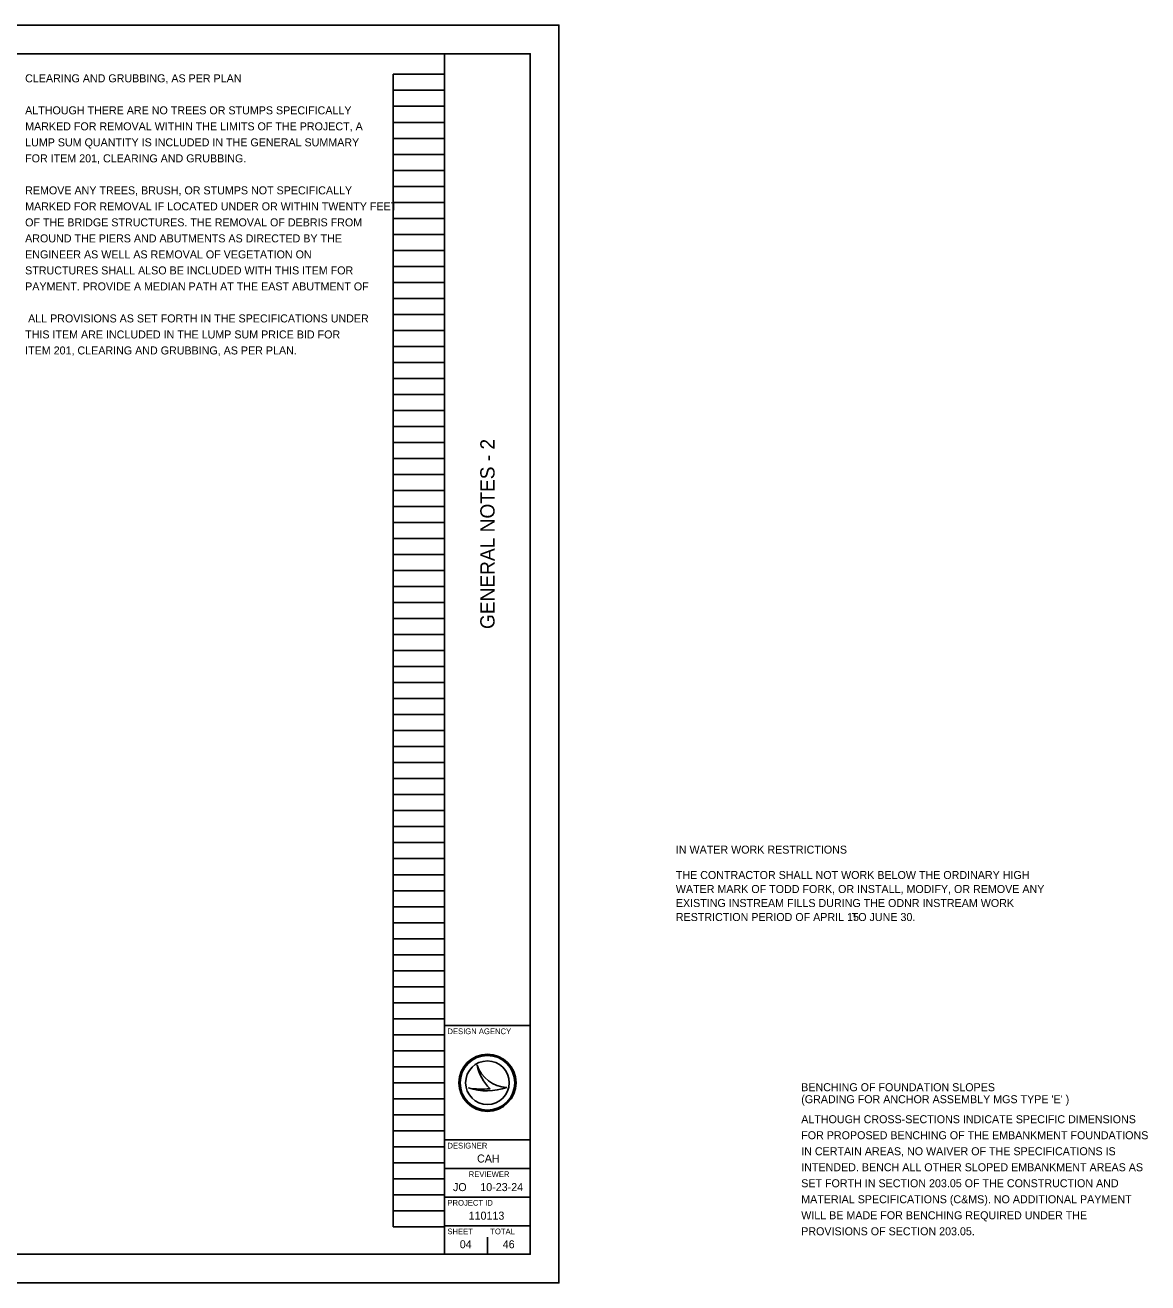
# Model space of a CAD drawing. Extents: x -10.1 to 44.3, y -20.7 to 25.5.
# Drawn here: x 24.66 to 44.31, y 0 to 22 of the extents above; entities that cross this region are included whole.
import ezdxf

# ---------------------------------------------------------------- set-up
doc = ezdxf.new("R2010")
doc.units = 0
for name, color, linetype in [('SH_Border', 7, 'Continuous'), ('SH_Cut_Line', 7, 'Continuous'), ('SH_Data', 7, 'Continuous'), ('SH_Text', 7, 'Continuous')]:
    doc.layers.add(name, color=color, linetype=linetype)

msp = doc.modelspace()

# ---------------------------------------------------------------- linework, layer by layer
at = {"layer": 'SH_Border'}
for p, q in [((32, 0.5), (32, 21.5)), ((32, 4.5), (33.5, 4.5)), ((32, 2.5), (33.5, 2.5)), ((32, 2), (33.5, 2)), ((32, 1.5), (33.5, 1.5)), ((32, 1), (33.5, 1))]:
    msp.add_line(p, q, dxfattribs=at)
msp.add_lwpolyline([(1.5, 21.5), (33.5, 21.5), (33.5, 0.5), (1.5, 0.5)], close=True, dxfattribs=at)
at = {"layer": 'SH_Cut_Line'}
msp.add_lwpolyline([(0, 0), (34, 0), (34, 22), (0, 22)], close=True, dxfattribs=at)
at = {"layer": 'SH_Data'}
for p, q in [((31.1, 0.98), (31.1, 21.14)), ((31.1, 21.14), (32, 21.14)), ((32, 0.98), (32, 21.14)), ((31.1, 20.86), (32, 20.86)), ((31.1, 20.58), (32, 20.58)), ((31.1, 20.3), (32, 20.3)), ((31.1, 20.02), (32, 20.02)), ((31.1, 19.74), (32, 19.74)), ((31.1, 19.46), (32, 19.46)), ((31.1, 19.18), (32, 19.18)), ((31.1, 18.9), (32, 18.9)), ((31.1, 18.62), (32, 18.62)), ((31.1, 18.34), (32, 18.34)), ((31.1, 18.06), (32, 18.06)), ((31.1, 17.78), (32, 17.78)), ((31.1, 17.5), (32, 17.5)), ((31.1, 17.22), (32, 17.22)), ((31.1, 16.94), (32, 16.94)), ((31.1, 16.66), (32, 16.66)), ((31.1, 16.38), (32, 16.38)), ((31.1, 16.1), (32, 16.1)), ((31.1, 15.82), (32, 15.82)), ((31.1, 15.54), (32, 15.54)), ((31.1, 15.26), (32, 15.26)), ((31.1, 14.98), (32, 14.98)), ((31.1, 14.7), (32, 14.7)), ((31.1, 14.42), (32, 14.42)), ((31.1, 14.14), (32, 14.14)), ((31.1, 13.86), (32, 13.86)), ((31.1, 13.58), (32, 13.58)), ((31.1, 13.3), (32, 13.3)), ((31.1, 13.02), (32, 13.02)), ((31.1, 12.74), (32, 12.74)), ((31.1, 12.46), (32, 12.46)), ((31.1, 12.18), (32, 12.18)), ((31.1, 11.9), (32, 11.9)), ((31.1, 11.62), (32, 11.62)), ((31.1, 11.34), (32, 11.34)), ((31.1, 11.06), (32, 11.06)), ((31.1, 10.78), (32, 10.78)), ((31.1, 10.5), (32, 10.5)), ((31.1, 10.22), (32, 10.22)), ((31.1, 9.94), (32, 9.94)), ((31.1, 9.66), (32, 9.66)), ((31.1, 9.38), (32, 9.38)), ((31.1, 9.1), (32, 9.1)), ((31.1, 8.82), (32, 8.82)), ((31.1, 8.54), (32, 8.54)), ((31.1, 8.26), (32, 8.26)), ((31.1, 7.98), (32, 7.98)), ((31.1, 7.7), (32, 7.7)), ((31.1, 7.42), (32, 7.42)), ((31.1, 7.14), (32, 7.14)), ((31.1, 6.86), (32, 6.86)), ((31.1, 6.58), (32, 6.58)), ((31.1, 6.3), (32, 6.3)), ((31.1, 6.02), (32, 6.02)), ((31.1, 5.74), (32, 5.74)), ((31.1, 5.46), (32, 5.46)), ((31.1, 5.18), (32, 5.18)), ((31.1, 4.9), (32, 4.9)), ((31.1, 4.62), (32, 4.62)), ((31.1, 4.34), (32, 4.34)), ((31.1, 4.06), (32, 4.06)), ((31.1, 3.78), (32, 3.78)), ((32.567, 3.81), (32.567, 3.81)), ((31.1, 3.5), (32, 3.5)), ((32.417, 3.41), (32.417, 3.41)), ((32.75, 3.5), (32.75, 3.5)), ((33.087, 3.419), (33.087, 3.419)), ((31.1, 3.22), (32, 3.22)), ((31.1, 2.94), (32, 2.94)), ((31.1, 2.66), (32, 2.66)), ((31.1, 2.38), (32, 2.38)), ((31.1, 2.1), (32, 2.1)), ((31.1, 1.82), (32, 1.82)), ((31.1, 1.54), (32, 1.54)), ((31.1, 1.26), (32, 1.26)), ((31.1, 0.98), (32, 0.98)), ((32.375, 0.675), (32.375, 0.675)), ((32.75, 0.5), (32.75, 0.8))]:
    msp.add_line(p, q, dxfattribs=at)
for radius in [0.5, 0.477, 0.477, 0.382]:
    msp.add_circle((32.75, 3.5), radius, dxfattribs=at)
for centre, radius, start, end in [((33.116, 3.998), 0.58, 198.9257, 198.9319), ((33.347, 3.97), 0.796, 191.6379, 191.6421), ((33.116, 3.998), 0.58, 198.9319, 267.1657), ((33.347, 3.97), 0.796, 191.6421, 226.0947), ((32.739, 4.37), 1.013, 251.4576, 290.0832), ((32.648, 4.654), 1.266, 259.4964, 259.4995), ((32.739, 4.37), 1.013, 251.4527, 251.4576), ((32.648, 4.654), 1.266, 259.4995, 276.6672)]:
    msp.add_arc(centre, radius, start, end, dxfattribs=at)

# ---------------------------------------------------------------- texts
msp.add_text('GENERAL NOTES - 2', height=0.25, rotation=90, dxfattribs=at).set_placement((32.875, 11.437))
for s, height, p in [('DESIGN AGENCY', 0.1, (32.05, 4.35)), ('DESIGNER', 0.1, (32.05, 2.35)), ('CAH', 0.14, (32.568, 2.105)), ('REVIEWER', 0.1, (32.422, 1.85)), ('JO', 0.14, (32.147, 1.605)), ('10-23-24', 0.14, (32.625, 1.605)), ('PROJECT ID', 0.1, (32.05, 1.35)), ('110113', 0.14, (32.421, 1.105)), ('SHEET', 0.1, (32.05, 0.85)), ('TOTAL', 0.1, (32.8, 0.85)), ('04', 0.14, (32.266, 0.605)), ('46', 0.14, (33.018, 0.605))]:
    msp.add_text(s, height=height, dxfattribs=at).set_placement(p)
at = {"layer": 'SH_Text'}
for s, p in [('CLEARING AND GRUBBING, AS PER PLAN', (24.66, 21)), ('ALTHOUGH THERE ARE NO TREES OR STUMPS SPECIFICALLY', (24.66, 20.44)), ('MARKED FOR REMOVAL WITHIN THE LIMITS OF THE PROJECT, A', (24.66, 20.16)), ('LUMP SUM QUANTITY IS INCLUDED IN THE GENERAL SUMMARY', (24.66, 19.88)), ('FOR ITEM 201, CLEARING AND GRUBBING.', (24.66, 19.6)), ('REMOVE ANY TREES, BRUSH, OR STUMPS NOT SPECIFICALLY', (24.66, 19.04)), ('MARKED FOR REMOVAL IF LOCATED UNDER OR WITHIN TWENTY FEET', (24.66, 18.76)), ('OF THE BRIDGE STRUCTURES. THE REMOVAL OF DEBRIS FROM', (24.66, 18.48)), ('AROUND THE PIERS AND ABUTMENTS AS DIRECTED BY THE', (24.66, 18.2)), ('ENGINEER AS WELL AS REMOVAL OF VEGETATION ON', (24.66, 17.92)), ('STRUCTURES SHALL ALSO BE INCLUDED WITH THIS ITEM FOR', (24.66, 17.64)), ('PAYMENT. PROVIDE A MEDIAN PATH AT THE EAST ABUTMENT OF', (24.66, 17.36)), (' ALL PROVISIONS AS SET FORTH IN THE SPECIFICATIONS UNDER', (24.66, 16.8)), ('THIS ITEM ARE INCLUDED IN THE LUMP SUM PRICE BID FOR', (24.66, 16.52)), ('ITEM 201, CLEARING AND GRUBBING, AS PER PLAN.', (24.66, 16.24)), ('IN WATER WORK RESTRICTIONS', (36.047, 7.508)), ('THE CONTRACTOR SHALL NOT WORK BELOW THE ORDINARY HIGH ', (36.047, 7.064)), ('WATER MARK OF TODD FORK, OR INSTALL, MODIFY, OR REMOVE ANY ', (36.047, 6.819)), ('EXISTING INSTREAM FILLS DURING THE ODNR INSTREAM WORK ', (36.047, 6.574)), ('RESTRICTION PERIOD OF APRIL 15 ', (36.047, 6.329)), ('TO JUNE 30. ', (39.125, 6.329)), ('BENCHING OF FOUNDATION SLOPES', (38.241, 3.352)), ("(GRADING FOR ANCHOR ASSEMBLY MGS TYPE 'E' )", (38.241, 3.142)), ('ALTHOUGH CROSS-SECTIONS INDICATE SPECIFIC DIMENSIONS', (38.241, 2.792)), ('FOR PROPOSED BENCHING OF THE EMBANKMENT FOUNDATIONS', (38.241, 2.512)), ('IN CERTAIN AREAS, NO WAIVER OF THE SPECIFICATIONS IS', (38.241, 2.232)), ('INTENDED. BENCH ALL OTHER SLOPED EMBANKMENT AREAS AS', (38.241, 1.952)), ('SET FORTH IN SECTION 203.05 OF THE CONSTRUCTION AND', (38.241, 1.672)), ('MATERIAL SPECIFICATIONS (C&MS). NO ADDITIONAL PAYMENT', (38.241, 1.392)), ('WILL BE MADE FOR BENCHING REQUIRED UNDER THE', (38.241, 1.112)), ('PROVISIONS OF SECTION 203.05.', (38.241, 0.832))]:
    msp.add_text(s, height=0.14, dxfattribs=at).set_placement(p)

doc.saveas('drawing.dxf')
